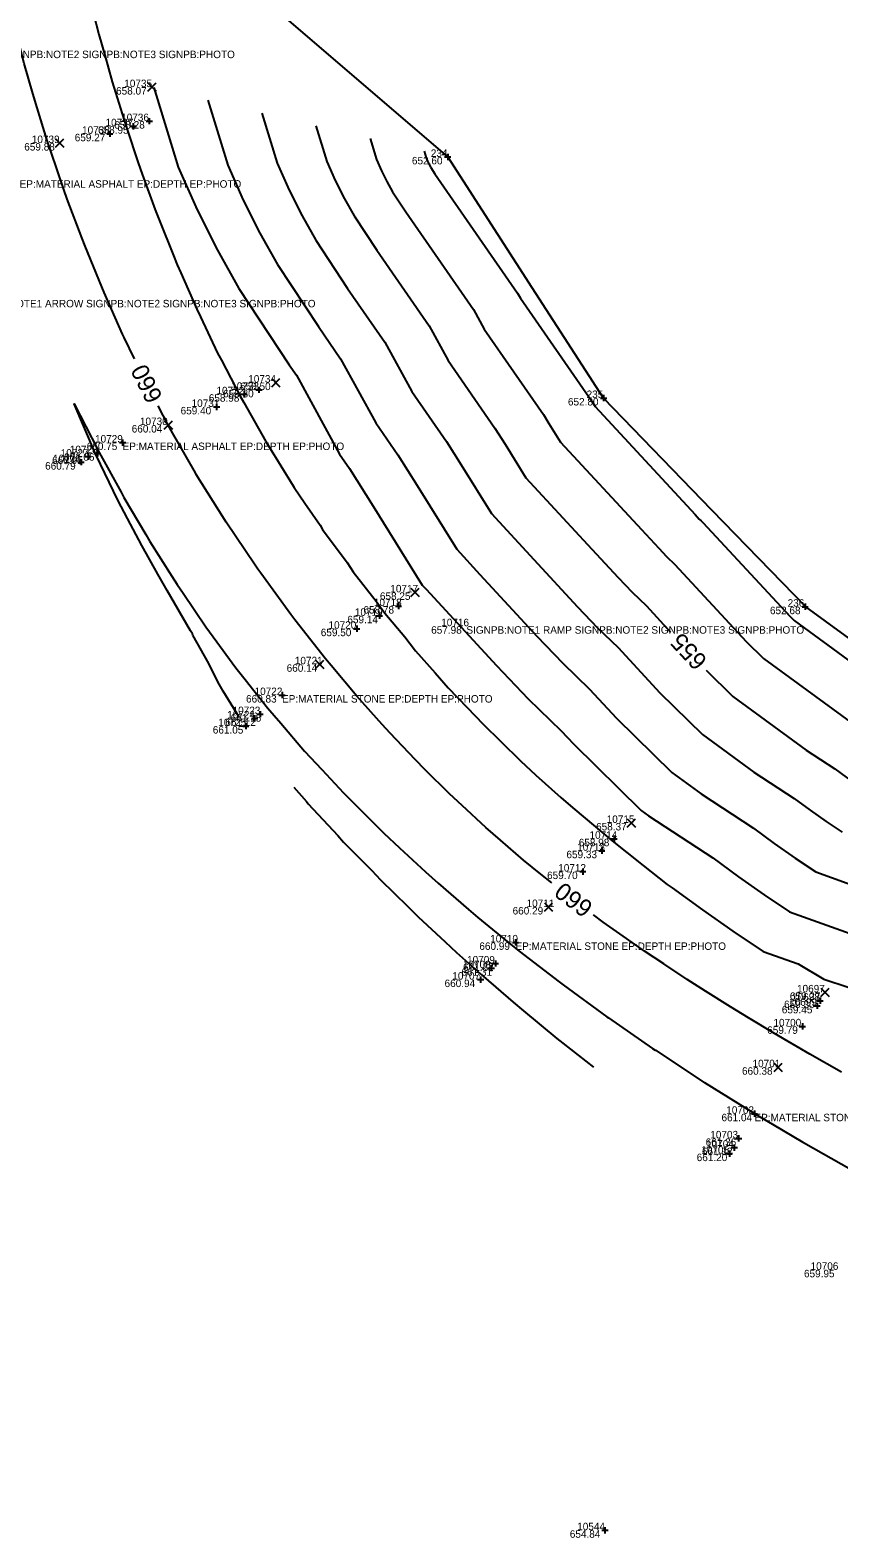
# Model space of a CAD drawing. Extents: x 2129350 to 2137777, y 657588 to 659885.
# Drawn here: x 2131945.9 to 2132075.7, y 658531.5 to 658773.5 of the extents above; entities that cross this region are included whole.
import ezdxf

# ---------------------------------------------------------------- set-up
doc = ezdxf.new("R2010")
doc.units = 0
for name, color, linetype in [('DT_X_Contour_Major', 7, 'Continuous'), ('DT_X_Contour_Minor', 7, 'Continuous'), ('DT_X_TIN_Hull', 7, 'Continuous'), ('SV_X_Random_Point', 7, 'Continuous'), ('SV_X_Shot_Marker', 7, 'Continuous'), ('SV_X_Text_Comment', 7, 'Continuous'), ('SV_X_Text_Elevation', 7, 'Continuous'), ('SV_X_Text_Name', 7, 'Continuous')]:
    doc.layers.add(name, color=color, linetype=linetype)

msp = doc.modelspace()

# ---------------------------------------------------------------- linework, layer by layer
at = {"layer": 'DT_X_Contour_Major'}
for points in [[(2131962.61, 658720.71), (2131960.95, 658724.15), (2131960.69, 658724.71), (2131957.72, 658731.4), (2131957.34, 658732.28), (2131954.67, 658738.81), (2131954.19, 658740.02), (2131951.82, 658746.35), (2131951.25, 658747.93), (2131949.16, 658754.04), (2131948.54, 658755.94), (2131946.96, 658761.01), (2131946.29, 658763.29), (2131944.91, 658768.14), (2131944.21, 658770.85), (2131943.03, 658775.47)], [(2131991.73, 658758.13), (2131993.48, 658752.41), (2131994.84, 658749.34), (2131996.33, 658746.43), (2131997.87, 658743.66), (2132001.49, 658738.18), (2132009.9, 658726.02), (2132012.93, 658720.48), (2132020.46, 658709.62), (2132022.08, 658707.03), (2132025.44, 658701.62), (2132035.33, 658690.94), (2132040.24, 658685.63), (2132042.47, 658683.3), (2132044.77, 658681.08), (2132048.65, 658676.9)], [(2132029.6, 658636.64), (2132027.85, 658638.05), (2132025.07, 658640.3), (2132021.37, 658643.49), (2132019, 658645.55), (2132015.18, 658649.08), (2132013.19, 658650.93), (2132009.28, 658654.8), (2132007.65, 658656.44), (2132003.66, 658660.64), (2132002.34, 658662.07), (2131998.32, 658666.58), (2131994.19, 658671.51), (2131993.25, 658672.62), (2131988.36, 658678.85), (2131987.69, 658679.7), (2131982.86, 658686.34), (2131982.38, 658687), (2131981.96, 658687.62), (2131977.32, 658694.5), (2131977.05, 658694.93), (2131972.53, 658702.2), (2131972.4, 658702.42), (2131968.5, 658709.22), (2131968.02, 658710.07), (2131968.01, 658710.1), (2131966.38, 658713.21)], [(2132054.38, 658670.76), (2132058.67, 658666.55), (2132070.44, 658657.94), (2132075, 658654.95), (2132076.82, 658653.62), (2132078.63, 658652.35), (2132080.45, 658651.14), (2132088.64, 658648.2), (2132099.95, 658639.94), (2132099.39, 658639.14), (2132099.81, 658638.51), (2132107.13, 658634.66), (2132122.8, 658629.83), (2132124.81, 658629), (2132126.87, 658628.2), (2132131.4, 658626.46), (2132139.96, 658623.87)], [(2132076.1, 658606.28), (2132071, 658609.15), (2132068.15, 658610.82), (2132065.35, 658612.49), (2132061.15, 658614.98), (2132058.29, 658616.74), (2132054.27, 658619.25), (2132051.32, 658621.13), (2132047.56, 658623.63), (2132044.49, 658625.67), (2132041.04, 658628.1), (2132037.84, 658630.36), (2132036.27, 658631.54)]]:
    msp.add_lwpolyline(points, dxfattribs=at)
at = {"layer": 'DT_X_Contour_Minor'}
for points in [[(2131955.96, 658776.29), (2131956.88, 658772.77), (2131957.82, 658769.49), (2131959.03, 658765.2), (2131960.62, 658760.06), (2131961.36, 658757.72), (2131963.22, 658752.2), (2131963.85, 658750.36), (2131965.95, 658744.66), (2131966.55, 658743.06), (2131968.85, 658737.31), (2131969.45, 658735.84), (2131970.03, 658734.54), (2131972.59, 658728.71), (2131973.18, 658727.47), (2131975.95, 658721.67), (2131976.55, 658720.53), (2131979.55, 658714.76), (2131980.14, 658713.72), (2131983.69, 658707.46), (2131984.12, 658706.77), (2131988.1, 658700.33), (2131988.25, 658700.1), (2131989.95, 658697.57), (2131992.39, 658694.05), (2131992.81, 658693.37), (2131996.73, 658688.06), (2131997.7, 658686.56), (2132001.39, 658681.86), (2132002.77, 658679.92), (2132005.98, 658676.1), (2132007.72, 658673.9), (2132010.87, 658670.37), (2132012.98, 658667.96), (2132016.01, 658664.78), (2132018.58, 658662.09), (2132021.39, 658659.31), (2132024.58, 658656.25), (2132027.04, 658653.95), (2132031.06, 658650.35), (2132032.97, 658648.67), (2132038.24, 658644.25), (2132039.26, 658643.4), (2132043.97, 658639.65), (2132044.03, 658639.59), (2132044.28, 658639.41), (2132048.1, 658636.4), (2132048.9, 658635.87), (2132053.79, 658632.29), (2132058.66, 658628.88), (2132063.54, 658625.65), (2132069.15, 658623.63), (2132073.28, 658621.19), (2132077.16, 658619.88)], [(2131965.7, 658764.27), (2131969.61, 658751.51), (2131972.64, 658744.66), (2131975.95, 658738.16), (2131979.38, 658732), (2131987.46, 658719.76), (2131988.59, 658718.14), (2131995.51, 658705.46), (2131997.11, 658703.16), (2132000.9, 658697.09), (2132008.77, 658684.44), (2132009.41, 658683.75), (2132020.69, 658671.53), (2132025.82, 658666.17), (2132031.11, 658661.06), (2132033.06, 658658.96), (2132043.96, 658648.25), (2132045.12, 658647.41), (2132055.43, 658640.64), (2132059.55, 658637.62), (2132063.66, 658634.75), (2132067.76, 658632.02), (2132086.3, 658625.36)], [(2131974.38, 658762.23), (2131977.57, 658751.81), (2131980.04, 658746.22), (2131982.74, 658740.91), (2131985.54, 658735.88), (2131992.14, 658725.9), (2131995.69, 658720.76), (2132001.32, 658710.46), (2132004.89, 658705.31), (2132007.96, 658700.4), (2132014.33, 658690.17), (2132018.05, 658686.15), (2132027.21, 658676.23), (2132031.37, 658671.88), (2132035.66, 658667.73), (2132040, 658663.06), (2132048.86, 658654.35), (2132053.56, 658650.92), (2132061.95, 658645.41), (2132065.3, 658642.95), (2132068.65, 658640.62), (2132071.99, 658638.39), (2132087.08, 658632.97)], [(2131983.05, 658760.18), (2131985.53, 658752.11), (2131987.44, 658747.78), (2131989.53, 658743.67), (2131991.7, 658739.77), (2131996.81, 658732.04), (2132002.8, 658723.39), (2132007.12, 658715.47), (2132012.67, 658707.47), (2132015.02, 658703.71), (2132019.89, 658695.89), (2132026.69, 658688.55), (2132033.72, 658680.93), (2132036.92, 658677.59), (2132040.22, 658674.41), (2132046.93, 658667.16), (2132053.77, 658660.45), (2132062, 658654.43), (2132068.47, 658650.18), (2132071.06, 658648.29), (2132073.64, 658646.48), (2132076.22, 658644.77)], [(2132000.41, 658756.09), (2132001.44, 658752.71), (2132002.25, 658750.9), (2132003.12, 658749.18), (2132004.03, 658747.55), (2132006.16, 658744.32), (2132017, 658728.65), (2132018.73, 658725.48), (2132028.24, 658711.78), (2132029.14, 658710.34), (2132031, 658707.34), (2132043.97, 658693.34), (2132046.75, 658690.33), (2132048.02, 658689.01), (2132049.32, 658687.75), (2132060.8, 658675.37), (2132063.57, 658672.64), (2132078.88, 658661.46)], [(2132009.09, 658754.04), (2132009.4, 658753.01), (2132009.65, 658752.46), (2132009.91, 658751.94), (2132010.19, 658751.44), (2132010.84, 658750.45), (2132024.1, 658731.28), (2132024.54, 658730.49), (2132036.02, 658713.93), (2132036.2, 658713.65), (2132036.56, 658713.07), (2132052.62, 658695.74), (2132053.27, 658695.03), (2132053.57, 658694.72), (2132053.87, 658694.42), (2132067.73, 658679.47), (2132068.47, 658678.74), (2132087.32, 658664.97)], [(2131979.41, 658663.25), (2131976.85, 658667.4), (2131975.99, 658668.91), (2131974.53, 658671.87), (2131971.99, 658676.39), (2131971.89, 658676.6), (2131971.61, 658677.1), (2131967.85, 658683.58), (2131966.35, 658686.19), (2131963.8, 658690.78), (2131961.49, 658695.13), (2131959.94, 658698.07), (2131957.17, 658703.83), (2131956.35, 658705.48), (2131952.91, 658713.54), (2131956.65, 658706.25), (2131956.93, 658705.71), (2131960.44, 658699.34), (2131960.91, 658698.51), (2131964.42, 658692.54), (2131965.08, 658691.44), (2131968.61, 658685.84), (2131969.46, 658684.52), (2131970.42, 658683.12), (2131974.06, 658677.75), (2131975.25, 658676.12), (2131978.89, 658671.15), (2131980.37, 658669.28), (2131983.94, 658664.75), (2131986.08, 658662.25), (2131989.9, 658657.8), (2131992.67, 658654.82), (2131996.14, 658651.1), (2131999.64, 658647.59), (2132002.61, 658644.63), (2132005.16, 658642.27), (2132009.31, 658638.39), (2132011.35, 658636.61), (2132016.2, 658632.37), (2132017.74, 658631.11), (2132023.26, 658626.56), (2132024.37, 658625.7), (2132030.77, 658620.75), (2132031.41, 658620.28), (2132038.42, 658615.16), (2132038.68, 658614.98), (2132045.78, 658610.07), (2132046.2, 658609.78), (2132046.21, 658609.78), (2132054.06, 658604.63), (2132054.12, 658604.6), (2132062.11, 658599.64), (2132062.14, 658599.62), (2132062.18, 658599.6), (2132065.04, 658597.92), (2132069.86, 658595.06), (2132070.02, 658594.97), (2132077.66, 658590.65)], [(2131988.2, 658652.01), (2131990.23, 658649.69), (2131990.49, 658649.35), (2131995.26, 658644.27), (2131996.17, 658643.19), (2132000.71, 658638.61), (2132002.09, 658637.11), (2132006.47, 658632.87), (2132008.16, 658631.18), (2132012.47, 658627.18), (2132014.3, 658625.46), (2132018.62, 658621.62), (2132023.39, 658617.52), (2132025.04, 658616.09), (2132030.41, 658611.67), (2132031.34, 658610.92), (2132036.26, 658607.07)]]:
    msp.add_lwpolyline(points, dxfattribs=at)
at = {"layer": 'DT_X_TIN_Hull'}
msp.add_lwpolyline([(2132390.69, 658692.25), (2132358.28, 658636.83), (2132322.29, 658626.46), (2132291.71, 658634.61), (2132276.48, 658622.77), (2132238.34, 658616.87), (2132195.61, 658626.85), (2132174.59, 658630.52), (2132149.97, 658634.81), (2132109.6, 658652.44), (2132090.5, 658666.29), (2132070.35, 658680.96), (2132055.27, 658696.47), (2132037.9, 658714.45), (2132026.46, 658732.15), (2132012.89, 658753.14), (2131962.28, 658796.59)], dxfattribs=at)
at = {"layer": 'SV_X_Random_Point'}
for p, q in [((2131964.74, 658763.68), (2131966.07, 658765.01)), ((2131964.74, 658765.01), (2131966.07, 658763.68)), ((2131949.91, 658754.69), (2131951.25, 658756.03)), ((2131949.91, 658756.03), (2131951.25, 658754.69)), ((2131984.63, 658716.25), (2131985.96, 658717.59)), ((2131984.63, 658717.59), (2131985.96, 658716.25)), ((2131967.37, 658709.44), (2131968.7, 658710.78)), ((2131967.37, 658710.78), (2131968.7, 658709.44)), ((2132006.96, 658682.59), (2132008.29, 658683.92)), ((2132006.96, 658683.92), (2132008.29, 658682.59)), ((2131991.65, 658671.05), (2131992.98, 658672.39)), ((2131991.65, 658672.39), (2131992.98, 658671.05)), ((2132041.69, 658645.59), (2132043.02, 658646.92)), ((2132041.69, 658646.92), (2132043.02, 658645.59)), ((2132028.4, 658632.11), (2132029.73, 658633.44)), ((2132028.4, 658633.44), (2132029.73, 658632.11)), ((2132072.77, 658618.4), (2132074.11, 658619.74)), ((2132072.77, 658619.74), (2132074.11, 658618.4)), ((2132065.26, 658606.4), (2132066.59, 658607.73)), ((2132065.26, 658607.73), (2132066.59, 658606.4))]:
    msp.add_line(p, q, dxfattribs=at)
at = {"layer": 'SV_X_Shot_Marker'}
for p, q in [((2131964.98, 658759.38), (2131964.98, 658758.38)), ((2131958.15, 658756.85), (2131959.15, 658756.85)), ((2131958.65, 658757.35), (2131958.65, 658756.35)), ((2131958.65, 658756.85), (2131958.65, 658756.85)), ((2131961.91, 658758.06), (2131962.91, 658758.06)), ((2131962.41, 658758.56), (2131962.41, 658757.56)), ((2131962.41, 658758.06), (2131962.41, 658758.06)), ((2131964.48, 658758.88), (2131965.48, 658758.88)), ((2131964.98, 658758.88), (2131964.98, 658758.88)), ((2132012.39, 658753.14), (2132013.39, 658753.14)), ((2132012.89, 658753.64), (2132012.89, 658752.64)), ((2132012.89, 658753.14), (2132012.89, 658753.14)), ((2131982.08, 658715.76), (2131983.08, 658715.76)), ((2131982.58, 658716.26), (2131982.58, 658715.26)), ((2131982.58, 658715.76), (2131982.58, 658715.76)), ((2131975.78, 658713.52), (2131975.78, 658712.52)), ((2131979.7, 658715.05), (2131980.7, 658715.05)), ((2131980.2, 658715.55), (2131980.2, 658714.55)), ((2131980.2, 658715.05), (2131980.2, 658715.05)), ((2132037.41, 658714.45), (2132038.41, 658714.45)), ((2132037.91, 658714.95), (2132037.91, 658713.95)), ((2132037.91, 658714.45), (2132037.91, 658714.45)), ((2131975.28, 658713.02), (2131976.28, 658713.02)), ((2131975.78, 658713.02), (2131975.78, 658713.02)), ((2131956.65, 658706.09), (2131956.65, 658705.09)), ((2131960.19, 658707.3), (2131961.19, 658707.3)), ((2131960.69, 658707.8), (2131960.69, 658706.8)), ((2131960.69, 658707.3), (2131960.69, 658707.3)), ((2131953.53, 658704.16), (2131954.53, 658704.16)), ((2131954.03, 658704.66), (2131954.03, 658703.66)), ((2131954.03, 658704.16), (2131954.03, 658704.16)), ((2131954.67, 658705.04), (2131955.67, 658705.04)), ((2131955.17, 658705.54), (2131955.17, 658704.54)), ((2131955.17, 658705.04), (2131955.17, 658705.04)), ((2131956.15, 658705.59), (2131957.15, 658705.59)), ((2131956.65, 658705.59), (2131956.65, 658705.59)), ((2132001.44, 658679.5), (2132002.44, 658679.5)), ((2132001.94, 658680), (2132001.94, 658679)), ((2132001.94, 658679.5), (2132001.94, 658679.5)), ((2132004.49, 658681.06), (2132005.49, 658681.06)), ((2132004.99, 658681.56), (2132004.99, 658680.56)), ((2132004.99, 658681.06), (2132004.99, 658681.06)), ((2132069.76, 658680.96), (2132070.76, 658680.96)), ((2132070.26, 658681.46), (2132070.26, 658680.46)), ((2132070.26, 658680.96), (2132070.26, 658680.96)), ((2131997.77, 658677.43), (2131998.77, 658677.43)), ((2131998.27, 658677.93), (2131998.27, 658676.93)), ((2131998.27, 658677.43), (2131998.27, 658677.43)), ((2131985.79, 658666.78), (2131986.79, 658666.78)), ((2131986.29, 658667.28), (2131986.29, 658666.28)), ((2131986.29, 658666.78), (2131986.29, 658666.78)), ((2131981.38, 658663.03), (2131982.38, 658663.03)), ((2131981.88, 658663.53), (2131981.88, 658662.53)), ((2131981.88, 658663.03), (2131981.88, 658663.03)), ((2131982.26, 658663.72), (2131983.26, 658663.72)), ((2131982.76, 658664.22), (2131982.76, 658663.22)), ((2131982.76, 658663.72), (2131982.76, 658663.72)), ((2131979.97, 658661.8), (2131980.97, 658661.8)), ((2131980.47, 658662.3), (2131980.47, 658661.3)), ((2131980.47, 658661.8), (2131980.47, 658661.8)), ((2132039.09, 658643.72), (2132040.09, 658643.72)), ((2132039.59, 658644.22), (2132039.59, 658643.22)), ((2132039.59, 658643.72), (2132039.59, 658643.72)), ((2132037.12, 658641.8), (2132038.12, 658641.8)), ((2132037.62, 658642.3), (2132037.62, 658641.3)), ((2132037.62, 658641.8), (2132037.62, 658641.8)), ((2132034.07, 658638.45), (2132035.07, 658638.45)), ((2132034.57, 658638.95), (2132034.57, 658637.95)), ((2132034.57, 658638.45), (2132034.57, 658638.45)), ((2132023.26, 658627.09), (2132024.26, 658627.09)), ((2132023.76, 658627.59), (2132023.76, 658626.59)), ((2132023.76, 658627.09), (2132023.76, 658627.09)), ((2132020.55, 658624.21), (2132020.55, 658623.21)), ((2132018.16, 658621.62), (2132018.16, 658620.62)), ((2132019.37, 658622.95), (2132020.37, 658622.95)), ((2132019.87, 658623.45), (2132019.87, 658622.45)), ((2132019.87, 658622.95), (2132019.87, 658622.95)), ((2132020.05, 658623.71), (2132021.05, 658623.71)), ((2132020.55, 658623.71), (2132020.55, 658623.71)), ((2132017.66, 658621.12), (2132018.66, 658621.12)), ((2132018.16, 658621.12), (2132018.16, 658621.12)), ((2132071.68, 658616.91), (2132072.68, 658616.91)), ((2132072.16, 658617.74), (2132073.16, 658617.74)), ((2132072.18, 658617.41), (2132072.18, 658616.41)), ((2132072.18, 658616.91), (2132072.18, 658616.91)), ((2132072.66, 658618.24), (2132072.66, 658617.24)), ((2132072.66, 658617.74), (2132072.66, 658617.74)), ((2132069.82, 658614.12), (2132069.82, 658613.12)), ((2132069.32, 658613.62), (2132070.32, 658613.62)), ((2132069.82, 658613.62), (2132069.82, 658613.62)), ((2132061.62, 658599.59), (2132062.62, 658599.59)), ((2132062.12, 658600.09), (2132062.12, 658599.09)), ((2132062.12, 658599.59), (2132062.12, 658599.59)), ((2132059.07, 658595.64), (2132060.07, 658595.64)), ((2132059.57, 658596.14), (2132059.57, 658595.14)), ((2132059.57, 658595.64), (2132059.57, 658595.64)), ((2132057.62, 658593.19), (2132058.62, 658593.19)), ((2132058.12, 658593.69), (2132058.12, 658592.69)), ((2132058.12, 658593.19), (2132058.12, 658593.19)), ((2132058.39, 658594.16), (2132059.39, 658594.16)), ((2132058.89, 658594.66), (2132058.89, 658593.66)), ((2132058.89, 658594.16), (2132058.89, 658594.16)), ((2132037.62, 658532.76), (2132038.62, 658532.76)), ((2132038.12, 658533.26), (2132038.12, 658532.26)), ((2132038.12, 658532.76), (2132038.12, 658532.76))]:
    msp.add_line(p, q, dxfattribs=at)

# ---------------------------------------------------------------- texts
at = {"layer": 'DT_X_Contour_Major'}
for s, rotation, p in [('660', 116.7098, (2131967.2, 658714.57)), ('655', 133.0595, (2132054.71, 658672.43)), ('660', 142.5588, (2132036.42, 658633.13))]:
    msp.add_text(s, height=2.8, rotation=rotation, dxfattribs=at).set_placement(p)
at = {"layer": 'SV_X_Text_Comment'}
for s, p in [('SIGNPB:NOTE1 ARROW SIGNPB:NOTE2 SIGNPB:NOTE3 SIGNPB:PHOTO', (2131922.99, 658768.99)), ('EP:MATERIAL ASPHALT EP:DEPTH EP:PHOTO', (2131944.17, 658748.2)), ('SIGNPB:NOTE1 ARROW SIGNPB:NOTE2 SIGNPB:NOTE3 SIGNPB:PHOTO', (2131935.94, 658729)), ('EP:MATERIAL ASPHALT EP:DEPTH EP:PHOTO', (2131960.69, 658706.1)), ('SIGNPB:NOTE1 RAMP SIGNPB:NOTE2 SIGNPB:NOTE3 SIGNPB:PHOTO', (2132015.88, 658676.63)), ('EP:MATERIAL STONE EP:DEPTH EP:PHOTO', (2131986.29, 658665.58)), ('EP:MATERIAL STONE EP:DEPTH EP:PHOTO', (2132023.76, 658625.89)), ('EP:MATERIAL STONE EP:DEPTH EP:PHOTO', (2132062.12, 658598.39))]:
    msp.add_text(s, height=1.2, dxfattribs=at).set_placement(p)
at = {"layer": 'SV_X_Text_Elevation'}
for s, p in [('658.07', (2131959.65, 658763.14)), ('659.27', (2131953.01, 658755.65)), ('658.95', (2131956.75, 658756.86)), ('658.28', (2131959.35, 658757.68)), ('659.88', (2131944.91, 658754.16)), ('652.60', (2132007.14, 658751.94)), ('658.80', (2131976.83, 658714.56)), ('658.50', (2131979.55, 658715.72)), ('658.98', (2131974.53, 658713.86)), ('652.80', (2132032.18, 658713.25)), ('659.40', (2131970.01, 658711.82)), ('660.04', (2131962.16, 658708.91)), ('660.75', (2131954.94, 658706.1)), ('660.79', (2131948.26, 658702.96)), ('660.95', (2131949.38, 658703.84)), ('661.06', (2131951.27, 658704.39)), ('658.25', (2132002, 658682.06)), ('659.14', (2131996.77, 658678.3)), ('658.78', (2131999.36, 658679.86)), ('652.68', (2132064.61, 658679.76)), ('659.50', (2131992.51, 658676.23)), ('657.98', (2132010.23, 658676.63)), ('660.14', (2131987.03, 658670.52)), ('660.83', (2131980.51, 658665.58)), ('661.12', (2131977.18, 658661.83)), ('661.15', (2131978.05, 658662.52)), ('661.05', (2131975.17, 658660.6)), ('658.37', (2132036.7, 658645.06)), ('658.98', (2132033.92, 658642.52)), ('659.33', (2132031.94, 658640.6)), ('659.70', (2132028.83, 658637.25)), ('660.29', (2132023.3, 658631.57)), ('660.99', (2132017.96, 658625.89)), ('661.31', (2132015.1, 658621.75)), ('661.32', (2132015.35, 658622.51)), ('660.94', (2132012.38, 658619.92)), ('659.27', (2132067.8, 658617.87)), ('659.45', (2132066.51, 658615.71)), ('659.30', (2132066.87, 658616.54)), ('659.79', (2132064.17, 658612.42)), ('660.38', (2132060.12, 658605.86)), ('661.04', (2132056.83, 658598.39)), ('661.36', (2132054.29, 658594.44)), ('661.20', (2132052.85, 658591.99)), ('661.32', (2132053.69, 658592.96)), ('659.95', (2132070.07, 658573.35)), ('654.84', (2132032.48, 658531.55))]:
    msp.add_text(s, height=1.2, dxfattribs=at).set_placement(p)
at = {"layer": 'SV_X_Text_Name'}
for s, p in [('10735', (2131960.96, 658764.34)), ('10737', (2131957.96, 658758.06)), ('10736', (2131960.46, 658758.88)), ('10738', (2131954.19, 658756.85)), ('10739', (2131946.12, 658755.36)), ('234', (2132010.17, 658753.14)), ('10734', (2131980.86, 658716.92)), ('10732', (2131975.76, 658715.05)), ('10733', (2131978.13, 658715.76)), ('10731', (2131971.77, 658713.02)), ('235', (2132035.18, 658714.45)), ('10730', (2131963.48, 658710.11)), ('10729', (2131956.27, 658707.3)), ('10727', (2131950.76, 658705.04)), ('10728', (2131952.22, 658705.59)), ('10726', (2131949.54, 658704.16)), ('10717', (2132003.67, 658683.26)), ('10718', (2132001.03, 658681.06)), ('236', (2132067.45, 658680.96)), ('10719', (2131997.98, 658679.5)), ('10720', (2131993.75, 658677.43)), ('10716', (2132011.84, 658677.83)), ('10721', (2131988.34, 658671.72)), ('10722', (2131981.88, 658666.78)), ('10723', (2131978.35, 658663.72)), ('10725', (2131976.06, 658661.8)), ('10724', (2131977.48, 658663.03)), ('10715', (2132038.4, 658646.26)), ('10714', (2132035.64, 658643.72)), ('10713', (2132033.66, 658641.8)), ('10712', (2132030.62, 658638.45)), ('10711', (2132025.54, 658632.77)), ('10710', (2132019.7, 658627.09)), ('10708', (2132015.32, 658622.95)), ('10709', (2132015.99, 658623.71)), ('10707', (2132013.62, 658621.12)), ('10698', (2132068.16, 658617.74)), ('10697', (2132068.95, 658619.07)), ('10699', (2132067.68, 658616.91)), ('10700', (2132065.17, 658613.62)), ('10701', (2132061.81, 658607.06)), ('10702', (2132057.59, 658599.59)), ('10704', (2132054.35, 658594.16)), ('10703', (2132055.03, 658595.64)), ('10705', (2132053.58, 658593.19)), ('10706', (2132071.13, 658574.55)), ('10544', (2132033.67, 658532.76))]:
    msp.add_text(s, height=1.2, dxfattribs=at).set_placement(p)

doc.saveas('drawing.dxf')
